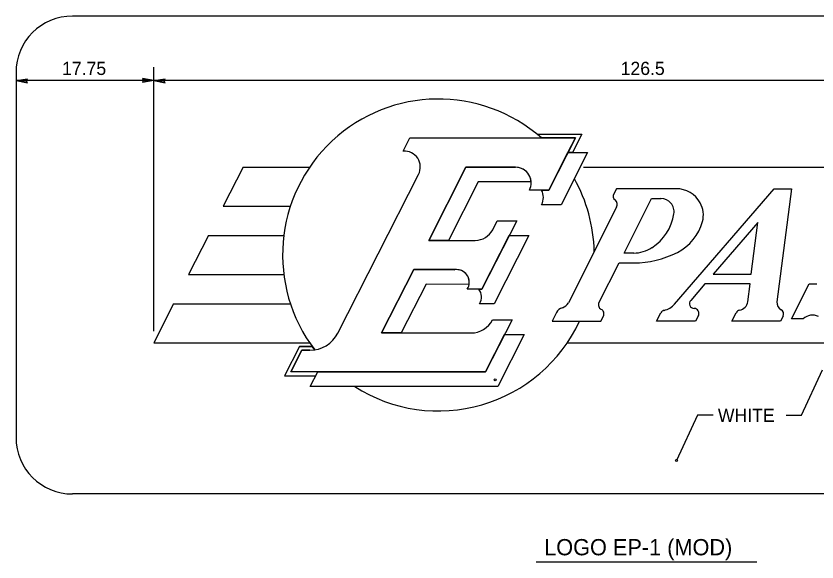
# Model space of a CAD drawing. Extents: x 10268197 to 10269179, y 2141503 to 2142677.
# Drawn here: x 10268589.78 to 10268632.35, y 2142209.17 to 2142238.15 of the extents above; entities that cross this region are included whole.
import ezdxf

# ---------------------------------------------------------------- set-up
doc = ezdxf.new("R2010")
doc.units = 0
for name, color, linetype in [('1', 7, 'Continuous'), ('2', 7, 'Continuous'), ('21', 7, 'Continuous'), ('3', 7, 'Continuous')]:
    doc.layers.add(name, color=color, linetype=linetype)

msp = doc.modelspace()

# ---------------------------------------------------------------- linework, layer by layer
at = {"layer": '1'}
for p, q in [((10268597.104, 2142221.415), (10268597.104, 2142235.426)), ((10268596.547, 2142234.732), (10268596.498, 2142234.626)), ((10268597.104, 2142234.722), (10268596.498, 2142234.626)), ((10268597.104, 2142234.722), (10268596.502, 2142234.839)), ((10268596.502, 2142234.839), (10268596.547, 2142234.732)), ((10268597.104, 2142234.722), (10268596.524, 2142234.682)), ((10268597.104, 2142234.722), (10268596.526, 2142234.783)), ((10268618.098, 2142228.903), (10268619.114, 2142230.896)), ((10268620.16, 2142230.896), (10268618.749, 2142228.129)), ((10268619.114, 2142230.896), (10268620.16, 2142230.896)), ((10268611.715, 2142226.239), (10268613.693, 2142230.12)), ((10268613.693, 2142230.12), (10268616.331, 2142230.12)), ((10268614.343, 2142229.344), (10268612.761, 2142226.239)), ((10268617.158, 2142229.344), (10268614.343, 2142229.344)), ((10268617.713, 2142228.903), (10268618.098, 2142228.903)), ((10268618.749, 2142228.129), (10268617.714, 2142228.129)), ((10268614.542, 2142223.651), (10268615.993, 2142226.497)), ((10268617.038, 2142226.497), (10268615.192, 2142222.874)), ((10268615.993, 2142226.497), (10268617.038, 2142226.497)), ((10268612.761, 2142226.239), (10268611.715, 2142226.239)), ((10268609.21, 2142221.322), (10268610.925, 2142224.686)), ((10268610.925, 2142224.686), (10268613.098, 2142224.679)), ((10268611.573, 2142223.908), (10268610.256, 2142221.322)), ((10268613.859, 2142223.9), (10268611.573, 2142223.908)), ((10268614.379, 2142223.651), (10268614.542, 2142223.651)), ((10268615.192, 2142222.874), (10268614.416, 2142222.874)), ((10268610.256, 2142221.322), (10268609.21, 2142221.322)), ((10268614.734, 2142219.252), (10268615.748, 2142221.242)), ((10268616.794, 2142221.242), (10268615.383, 2142218.475)), ((10268615.748, 2142221.242), (10268616.794, 2142221.242)), ((10268605.418, 2142218.475), (10268605.814, 2142219.252)), ((10268605.814, 2142219.252), (10268614.734, 2142219.252)), ((10268631.525, 2142216.966), (10268632.64, 2142219.374)), ((10268615.383, 2142218.475), (10268605.418, 2142218.475)), ((10268626.002, 2142216.966), (10268624.886, 2142214.559)), ((10268626.824, 2142216.966), (10268626.002, 2142216.966)), ((10268630.703, 2142216.966), (10268631.525, 2142216.966))]:
    msp.add_line(p, q, dxfattribs=at)
msp.add_lwpolyline([(10268617.472, 2142231.873), (10268619.844, 2142231.873), (10268619.347, 2142230.896), (10268619.114, 2142230.896), (10268619.51, 2142231.673), (10268617.708, 2142231.673)], close=True, dxfattribs=at)
for centre in [(10268615.251, 2142218.83), (10268624.886, 2142214.559)]:
    msp.add_circle(centre, 0.0518, dxfattribs=at)
for centre, radius, start, end in [((10268616.331, 2142229.292), 0.828, 3.5833, 90), ((10268616.981, 2142228.516), 0.828, 332.2089, 27.9127), ((10268613.196, 2142224.013), 0.673, 350.3502, 98.3344), ((10268613.849, 2142223.237), 0.673, 327.421, 37.9799)]:
    msp.add_arc(centre, radius, start, end, dxfattribs=at)
at = {"layer": '2'}
for p, q in [((10268653.784, 2142238.146), (10268592.784, 2142238.146)), ((10268589.784, 2142235.146), (10268589.784, 2142215.778)), ((10268597.104, 2142234.722), (10268589.784, 2142234.722)), ((10268649.465, 2142234.722), (10268597.104, 2142234.722)), ((10268610.358, 2142230.979), (10268610.711, 2142231.673)), ((10268610.711, 2142231.673), (10268619.51, 2142231.673)), ((10268617.472, 2142231.873), (10268619.844, 2142231.873)), ((10268619.51, 2142231.673), (10268618.1, 2142228.906)), ((10268619.844, 2142231.873), (10268619.347, 2142230.896)), ((10268618.098, 2142228.903), (10268619.114, 2142230.896)), ((10268620.16, 2142230.896), (10268618.749, 2142228.129)), ((10268619.114, 2142230.896), (10268620.16, 2142230.896)), ((10268601.85, 2142230.12), (10268600.796, 2142228.05)), ((10268601.85, 2142230.12), (10268605.384, 2142230.12)), ((10268613.693, 2142230.12), (10268611.715, 2142226.239)), ((10268611.715, 2142226.239), (10268613.693, 2142230.12)), ((10268616.331, 2142230.12), (10268613.693, 2142230.12)), ((10268613.693, 2142230.12), (10268616.331, 2142230.12)), ((10268619.941, 2142230.12), (10268649.465, 2142230.12)), ((10268606.88, 2142221.309), (10268611.175, 2142229.739)), ((10268614.343, 2142229.344), (10268612.761, 2142226.239)), ((10268617.158, 2142229.344), (10268614.343, 2142229.344)), ((10268621.687, 2142228.982), (10268621.546, 2142228.703)), ((10268624.857, 2142228.982), (10268621.687, 2142228.982)), ((10268624.777, 2142222.857), (10268630.062, 2142228.982)), ((10268630.062, 2142228.982), (10268630.994, 2142228.982)), ((10268630.994, 2142228.982), (10268630.219, 2142222.981)), ((10268618.1, 2142228.906), (10268617.064, 2142228.906)), ((10268617.713, 2142228.903), (10268618.098, 2142228.903)), ((10268618.749, 2142228.129), (10268617.714, 2142228.129)), ((10268622.093, 2142225.566), (10268623.558, 2142228.46)), ((10268623.558, 2142228.46), (10268624.057, 2142228.46)), ((10268600.796, 2142228.05), (10268604.365, 2142228.05)), ((10268621.696, 2142227.996), (10268619.134, 2142222.929)), ((10268616.388, 2142227.274), (10268614.542, 2142223.651)), ((10268615.113, 2142226.804), (10268615.353, 2142227.274)), ((10268615.353, 2142227.274), (10268616.388, 2142227.274)), ((10268629.196, 2142227.183), (10268626.833, 2142224.445)), ((10268628.842, 2142224.445), (10268629.196, 2142227.183)), ((10268600.005, 2142226.497), (10268598.95, 2142224.427)), ((10268600.005, 2142226.497), (10268604.015, 2142226.497)), ((10268614.542, 2142223.651), (10268615.993, 2142226.497)), ((10268617.038, 2142226.497), (10268615.192, 2142222.874)), ((10268615.993, 2142226.497), (10268617.038, 2142226.497)), ((10268611.715, 2142226.239), (10268614.191, 2142226.239)), ((10268612.761, 2142226.239), (10268611.715, 2142226.239)), ((10268622.606, 2142225.566), (10268622.093, 2142225.566)), ((10268620.76, 2142222.93), (10268621.83, 2142225.045)), ((10268621.83, 2142225.045), (10268622.606, 2142225.045)), ((10268598.95, 2142224.427), (10268604.015, 2142224.427)), ((10268610.925, 2142224.686), (10268609.21, 2142221.322)), ((10268609.21, 2142221.322), (10268610.925, 2142224.686)), ((10268613.196, 2142224.686), (10268610.925, 2142224.686)), ((10268610.925, 2142224.686), (10268613.098, 2142224.679)), ((10268626.833, 2142224.445), (10268628.842, 2142224.445)), ((10268611.573, 2142223.908), (10268610.256, 2142221.322)), ((10268613.859, 2142223.9), (10268611.573, 2142223.908)), ((10268626.385, 2142223.924), (10268625.634, 2142223.054)), ((10268628.789, 2142223.924), (10268626.385, 2142223.924)), ((10268628.667, 2142222.981), (10268628.789, 2142223.924)), ((10268630.99, 2142222.073), (10268631.93, 2142223.932)), ((10268631.93, 2142223.932), (10268632.345, 2142223.932)), ((10268614.542, 2142223.651), (10268613.763, 2142223.651)), ((10268614.379, 2142223.651), (10268614.542, 2142223.651)), ((10268598.159, 2142222.874), (10268597.104, 2142220.804)), ((10268598.159, 2142222.874), (10268604.365, 2142222.874)), ((10268615.192, 2142222.874), (10268614.416, 2142222.874)), ((10268618.504, 2142222.403), (10268618.272, 2142221.943)), ((10268620.859, 2142221.943), (10268621, 2142222.221)), ((10268623.825, 2142221.942), (10268624.05, 2142222.388)), ((10268626.048, 2142222.244), (10268625.895, 2142221.942)), ((10268627.819, 2142221.942), (10268628.047, 2142222.395)), ((10268630.543, 2142222.212), (10268630.407, 2142221.942)), ((10268616.143, 2142222.018), (10268614.734, 2142219.252)), ((10268615.108, 2142222.018), (10268616.143, 2142222.018)), ((10268618.272, 2142221.943), (10268620.859, 2142221.943)), ((10268625.895, 2142221.942), (10268623.825, 2142221.942)), ((10268630.407, 2142221.942), (10268627.819, 2142221.942)), ((10268631.619, 2142222.073), (10268630.99, 2142222.073)), ((10268609.21, 2142221.322), (10268613.96, 2142221.322)), ((10268610.256, 2142221.322), (10268609.21, 2142221.322)), ((10268614.734, 2142219.252), (10268615.748, 2142221.242)), ((10268616.794, 2142221.242), (10268615.383, 2142218.475)), ((10268615.748, 2142221.242), (10268616.794, 2142221.242)), ((10268597.104, 2142220.804), (10268605.384, 2142220.804)), ((10268604.843, 2142220.612), (10268604.045, 2142219.044)), ((10268604.843, 2142220.612), (10268605.519, 2142220.612)), ((10268619.077, 2142220.804), (10268644.718, 2142220.804)), ((10268604.383, 2142219.252), (10268604.97, 2142220.405)), ((10268604.97, 2142220.405), (10268604.383, 2142219.252)), ((10268604.97, 2142220.405), (10268605.405, 2142220.405)), ((10268605.405, 2142220.405), (10268604.97, 2142220.405)), ((10268614.734, 2142219.252), (10268604.383, 2142219.252)), ((10268605.418, 2142218.475), (10268605.814, 2142219.252)), ((10268605.814, 2142219.252), (10268614.734, 2142219.252)), ((10268604.045, 2142219.044), (10268605.708, 2142219.044)), ((10268615.383, 2142218.475), (10268605.418, 2142218.475)), ((10268653.784, 2142212.778), (10268592.784, 2142212.778))]:
    msp.add_line(p, q, dxfattribs=at)
for centre, radius, start, end in [((10268592.784, 2142235.146), 3, 90, 180), ((10268612.231, 2142225.462), 8.281, 48.5904, 217.4725), ((10268610.414, 2142230.127), 0.854, 332.9998, 93.8045), ((10268616.331, 2142229.292), 0.828, 332.2089, 90), ((10268616.331, 2142229.292), 0.828, 3.5833, 90), ((10268612.231, 2142225.462), 8.281, 1.2967, 29.2778), ((10268616.981, 2142228.516), 0.828, 332.2089, 27.9127), ((10268614.191, 2142227.274), 1.035, 270, 332.9883), ((10268613.196, 2142224.013), 0.673, 350.3502, 98.3344), ((10268613.196, 2142224.013), 0.673, 327.421, 90), ((10268613.849, 2142223.237), 0.673, 327.421, 37.9799), ((10268612.231, 2142225.462), 8.281, 237.5383, 334.8493), ((10268613.96, 2142222.616), 1.294, 270, 332.5096), ((10268605.405, 2142222.061), 1.656, 270, 332.9991), ((10268592.784, 2142215.778), 3, 180, 270)]:
    msp.add_arc(centre, radius, start, end, dxfattribs=at)
for centre, major_axis, start_param, end_param in [((10268624.857, 2142227.496), (0, 1.486), 5.226065, 6.283185), ((10268621.776, 2142228.585), (0, -0.261), 4.240773, 5.605302), ((10268621.419, 2142228.138), (0, -0.313), 1.099604, 2.46371), ((10268624.056, 2142227.757), (0, -0.704), 1.415043, 3.141593), ((10268625.014, 2142227.585), (0, 1.303), 4.445482, 5.226065), ((10268622.19, 2142228.052), (0, -2.607), 0.565847, 1.415043), ((10268623.766, 2142227.929), (0, -2.607), 0.465011, 1.30389), ((10268622.606, 2142227.392), (0, -1.825), 0, 0.565847), ((10268622.606, 2142230.259), (0, -5.214), 0, 0.465011), ((10268625.829, 2142222.884), (0, 0.261), 0.854904, 3.118676), ((10268618.965, 2142222.166), (0, -0.521), 3.428379, 4.240701), ((10268618.673, 2142223.166), (0, -0.521), 0.286787, 1.099486), ((10268620.99, 2142222.812), (0, 0.261), 1.099355, 2.701477), ((10268623.996, 2142223.542), (0, -1.043), 0.22194, 0.855152), ((10268625.817, 2142222.363), (0, 0.261), 4.240773, 6.260268), ((10268628.154, 2142223.049), (0, -0.521), 0.161263, 1.440999), ((10268630.629, 2142222.928), (0, 0.417), 1.441439, 2.650585), ((10268620.769, 2142222.34), (0, 0.261), 4.241567, 5.84307), ((10268624.281, 2142222.271), (0, -0.261), 3.363532, 4.241567), ((10268628.278, 2142222.277), (0, -0.261), 3.302856, 4.241567), ((10268630.312, 2142222.33), (0, 0.261), 4.240773, 5.792177), ((10268632.115, 2142221.541), (0, -0.73), 2.69443, 3.895387)]:
    msp.add_ellipse(centre, major_axis=major_axis, ratio=0.992614, start_param=start_param, end_param=end_param, dxfattribs=at)
at = {"layer": '21'}
for p, q in [((10268589.784, 2142234.722), (10268590.39, 2142234.818)), ((10268589.784, 2142234.722), (10268590.364, 2142234.763)), ((10268589.784, 2142234.722), (10268590.386, 2142234.606)), ((10268589.784, 2142234.722), (10268590.363, 2142234.662)), ((10268590.342, 2142234.713), (10268590.39, 2142234.818)), ((10268590.386, 2142234.606), (10268590.342, 2142234.713)), ((10268597.104, 2142234.722), (10268597.709, 2142234.818)), ((10268597.104, 2142234.722), (10268597.684, 2142234.763)), ((10268597.104, 2142234.722), (10268597.706, 2142234.606)), ((10268597.104, 2142234.722), (10268597.682, 2142234.662)), ((10268597.661, 2142234.713), (10268597.709, 2142234.818)), ((10268597.706, 2142234.606), (10268597.661, 2142234.713)), ((10268617.425, 2142209.168), (10268629.144, 2142209.168))]:
    msp.add_line(p, q, dxfattribs=at)
at = {"layer": '3'}
msp.add_lwpolyline([(10268605.519, 2142220.612), (10268604.843, 2142220.612), (10268604.045, 2142219.044), (10268605.708, 2142219.044), (10268605.814, 2142219.252), (10268604.383, 2142219.252), (10268604.97, 2142220.405), (10268605.405, 2142220.405), (10268605.659, 2142220.425)], close=True, dxfattribs=at)

# ---------------------------------------------------------------- texts
at = {"layer": '1'}
for s, height, p in [('17.75', 0.7, (10268592.232, 2142235.017)), ('126.5', 0.7, (10268621.913, 2142235.017)), ('WHITE', 0.7, (10268627.08, 2142216.603)), ('LOGO EP-1 (MOD)', 0.8624, (10268617.849, 2142209.522))]:
    msp.add_text(s, height=height, dxfattribs=at).set_placement(p)

doc.saveas('drawing.dxf')
